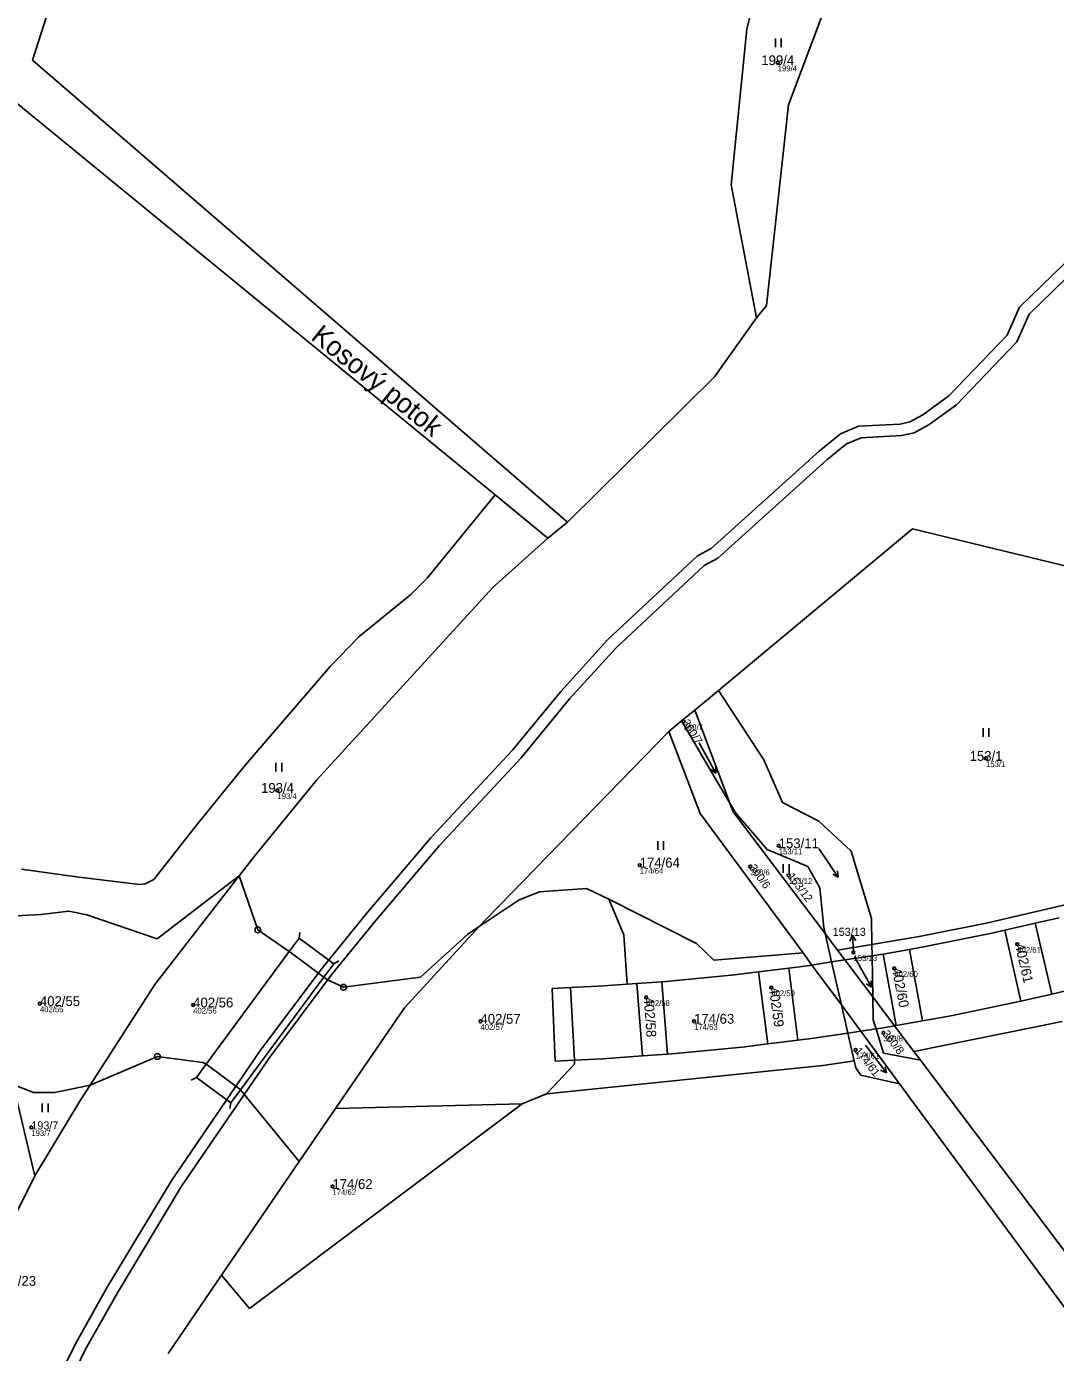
# Model space of a CAD drawing. Extents: x -868010 to -864567, y -1041968 to -1040406.
# Drawn here: x -867083.8 to -866905.6, y -1041242.1 to -1041012.6 of the extents above; entities that cross this region are included whole.
import ezdxf

# ---------------------------------------------------------------- set-up
doc = ezdxf.new("R2010")
doc.units = 0
for name, color, linetype in [('Definiční body', 7, 'Continuous'), ('Hranice parcel', 7, 'Continuous'), ('Parcelní čísla', 7, 'Continuous'), ('Pop  PČ popisy', 7, 'Continuous'), ('Vnitřní kresba', 7, 'Continuous'), ('Věcná břemena k části', 7, 'Continuous'), ('Značky bodu BP', 7, 'Continuous'), ('Značky kultur', 7, 'Continuous')]:
    doc.layers.add(name, color=color, linetype=linetype)

msp = doc.modelspace()

# ---------------------------------------------------------------- linework, layer by layer
at = {"layer": 'Definiční body'}
for centre in [(-866953.73, -1041018.85994), (-866970.03, -1041132.88994), (-866917.66, -1041139.30994), (-867040.36, -1041144.83994), (-866953.56, -1041154.41994), (-866977.63, -1041157.77994), (-866958.47, -1041158.02994), (-866951.83, -1041159.53994), (-866912.25, -1041171.46994), (-866940.61, -1041172.88994), (-866933.55, -1041175.64994), (-866954.84, -1041178.96994), (-867081.49, -1041181.74994), (-866976.5, -1041180.66994), (-867054.95, -1041181.98994), (-867005.2, -1041184.81994), (-866968.21, -1041184.80994), (-866935.42, -1041186.79994), (-866940.24, -1041189.77994), (-867082.98, -1041203.18994), (-867030.83, -1041213.41994)]:
    msp.add_circle(centre, 0.25, dxfattribs=at)
at = {"layer": 'Hranice parcel'}
for p, q in [((-867082.76, -1041018.41), (-867069.5, -1040976.72)), ((-866956.53, -1041002.58), (-866959.05, -1041013.05)), ((-866951.89, -1041026.16), (-866945.61, -1041009.62)), ((-866959.05, -1041013.05), (-866961.8, -1041040.03)), ((-866990.14, -1041098.41), (-867082.76, -1041018.41)), ((-867002.66, -1041093.69), (-867091.88, -1041020.67)), ((-866955.7, -1041060.91), (-866951.89, -1041026.16)), ((-866961.8, -1041040.03), (-866957.38, -1041063.05)), ((-866957.38, -1041063.05), (-866955.7, -1041060.91)), ((-866957.38, -1041063.05), (-866964.69, -1041073.26)), ((-866964.69, -1041073.26), (-866990.14, -1041098.41)), ((-867014.44, -1041108.08), (-867002.66, -1041093.69)), ((-867002.66, -1041093.69), (-866993.56, -1041101.15)), ((-866990.14, -1041098.41), (-866993.56, -1041101.15)), ((-866993.56, -1041101.15), (-867003.04, -1041109.72)), ((-866930.4, -1041099.56), (-866964, -1041127.54)), ((-866899.09, -1041107.19), (-866930.4, -1041099.56)), ((-867017.25, -1041110.9), (-867014.44, -1041108.08)), ((-867003.04, -1041109.72), (-867033.51, -1041142.99)), ((-867026.18, -1041118.21), (-867017.25, -1041110.9)), ((-867031.22, -1041123.37), (-867026.18, -1041118.21)), ((-867045.88, -1041140.4), (-867031.22, -1041123.37)), ((-866964, -1041127.54), (-866968.08, -1041130.93)), ((-866956.12, -1041139.57), (-866964, -1041127.54)), ((-866970.39, -1041132.82), (-866968.08, -1041130.93)), ((-866968.08, -1041130.93), (-866962, -1041147.03)), ((-866970.39, -1041132.82), (-866972.58, -1041134.62)), ((-866962, -1041147.03), (-866970.39, -1041132.82)), ((-866972.58, -1041134.62), (-867004.12, -1041167.01)), ((-866967.16, -1041148.83), (-866972.58, -1041134.62)), ((-867054.17, -1041150.56), (-867045.88, -1041140.4)), ((-866952.89, -1041146.93), (-866956.12, -1041139.57)), ((-867033.51, -1041142.99), (-867044.34, -1041156.21)), ((-866962, -1041147.03), (-866961.42, -1041148.56)), ((-866960.94, -1041148.82), (-866962, -1041147.03)), ((-866946.63, -1041150.18), (-866952.89, -1041146.93)), ((-866949.34, -1041172.98), (-866967.16, -1041148.83)), ((-866961.42, -1041148.56), (-866945.53, -1041169.61)), ((-866955.53, -1041155.07), (-866960.94, -1041148.82)), ((-867061.75, -1041160.24), (-867054.17, -1041150.56)), ((-866941.03, -1041155.38), (-866946.63, -1041150.18)), ((-867047.01, -1041159.66), (-867044.34, -1041156.21)), ((-866948.49, -1041158), (-866955.53, -1041155.07)), ((-866937.5, -1041167), (-866941.03, -1041155.38)), ((-867084.68, -1041158.49), (-867075.15, -1041159.79)), ((-866946.42, -1041161.69), (-866948.49, -1041158)), ((-867075.15, -1041159.79), (-867064.26, -1041161.14)), ((-867064.26, -1041161.14), (-867063.25, -1041161)), ((-867063.25, -1041161), (-867061.75, -1041160.24)), ((-867047.01, -1041159.66), (-867061.59, -1041178.47)), ((-867061.16, -1041170.53), (-867047.01, -1041159.66)), ((-867047.01, -1041159.66), (-867043.78, -1041168.98)), ((-866998.49, -1041163.81), (-866994.96, -1041162.41)), ((-866994.96, -1041162.41), (-866986.85, -1041161.84)), ((-866986.85, -1041161.84), (-866982.98, -1041163.69)), ((-866945.77, -1041168.59), (-866946.42, -1041161.69)), ((-867005.41, -1041168.41), (-866998.49, -1041163.81)), ((-866982.98, -1041163.69), (-866967.78, -1041171.35)), ((-866982.98, -1041163.69), (-866980.36, -1041169.82)), ((-866917.35, -1041167.76), (-866902.75, -1041164.39)), ((-867092.92, -1041166.93), (-867081.27, -1041166.31)), ((-867081.27, -1041166.31), (-867076.5, -1041165.75)), ((-867076.5, -1041165.75), (-867073.35, -1041166.37)), ((-867073.35, -1041166.37), (-867061.16, -1041170.53)), ((-867005.41, -1041168.41), (-867004.12, -1041167.01)), ((-866937.42, -1041171.51), (-866937.5, -1041167)), ((-866929.26, -1041170.14), (-866917.35, -1041167.76)), ((-866914.4, -1041169.04), (-866909.15, -1041167.84)), ((-866909.15, -1041167.84), (-866906.26, -1041180.09)), ((-867043.78, -1041168.98), (-867038.31, -1041172.75)), ((-867018.38, -1041182.48), (-867005.41, -1041168.41)), ((-867015.56, -1041177.2), (-867007.47, -1041169.78)), ((-867007.47, -1041169.78), (-867005.41, -1041168.41)), ((-866980.36, -1041169.82), (-866979.81, -1041178.4)), ((-866945.53, -1041169.61), (-866945.77, -1041168.59)), ((-866944.4, -1041174.54), (-866945.53, -1041169.61)), ((-866945.53, -1041169.61), (-866943.35, -1041172.51)), ((-866937.42, -1041171.51), (-866929.26, -1041170.14)), ((-866914.4, -1041169.04), (-866911.65, -1041181.34)), ((-866967.78, -1041171.35), (-866964.81, -1041174.22)), ((-866937.42, -1041171.51), (-866943.35, -1041172.51)), ((-866943.35, -1041172.51), (-866942.09, -1041174.19)), ((-866937.38, -1041173.46), (-866937.42, -1041171.51)), ((-866935.47, -1041173.17), (-866930.93, -1041172.36)), ((-866928.65, -1041184.72), (-866930.93, -1041172.36)), ((-867038.31, -1041172.75), (-867038.15, -1041172.86)), ((-867038.15, -1041172.86), (-867032.49, -1041177.07)), ((-866964.81, -1041174.22), (-866949.34, -1041172.98)), ((-866947.8, -1041175.07), (-866949.34, -1041172.98)), ((-866944.4, -1041174.54), (-866942.7, -1041181.98)), ((-866937.25, -1041180.6), (-866942.09, -1041174.19)), ((-866937.25, -1041180.6), (-866937.38, -1041173.46)), ((-866935.47, -1041173.17), (-866933.23, -1041185.53)), ((-867032.49, -1041177.07), (-867032.33, -1041177.18)), ((-866957.06, -1041176.27), (-866951.81, -1041175.62)), ((-866955.45, -1041188.74), (-866957.06, -1041176.27)), ((-866951.81, -1041175.62), (-866950.24, -1041188.09)), ((-866942.7, -1041181.98), (-866947.8, -1041175.07)), ((-867061.59, -1041178.47), (-867072.8, -1041195.85)), ((-867032.33, -1041177.18), (-867031.71, -1041177.62)), ((-867031.71, -1041177.62), (-867028.91, -1041178.93)), ((-867028.91, -1041178.93), (-867015.56, -1041177.2)), ((-866984.83, -1041178.76), (-866989.6, -1041178.99)), ((-866988.94, -1041191.53), (-866989.6, -1041178.99)), ((-866979.81, -1041178.4), (-866984.83, -1041178.76)), ((-866978.14, -1041178.28), (-866973.8, -1041177.97)), ((-866977.14, -1041190.81), (-866978.14, -1041178.28)), ((-866973.8, -1041177.97), (-866972.83, -1041190.51)), ((-866937.18, -1041184.59), (-866937.25, -1041180.6)), ((-866933.49, -1041185.58), (-866937.25, -1041180.6)), ((-866911.65, -1041181.34), (-866906.26, -1041180.09)), ((-867030.33, -1041199.93), (-867018.38, -1041182.48)), ((-866942.7, -1041181.98), (-866941.58, -1041186.86)), ((-866939.35, -1041186.52), (-866942.7, -1041181.98)), ((-866936.71, -1041186.12), (-866937.18, -1041184.59)), ((-866935.42, -1041190.31), (-866936.71, -1041186.12)), ((-866933.49, -1041185.58), (-866930.14, -1041190.03)), ((-866933.23, -1041185.53), (-866928.65, -1041184.72)), ((-866930.14, -1041190.03), (-866904.46, -1041184.83)), ((-866955.45, -1041188.74), (-866950.24, -1041188.09)), ((-866941.58, -1041186.86), (-866940.48, -1041191.65)), ((-866939.35, -1041186.52), (-866932.62, -1041195.63)), ((-867061.15, -1041190.9), (-867072.8, -1041195.85)), ((-867053.3, -1041191.94), (-867061.15, -1041190.9)), ((-866977.14, -1041190.81), (-866972.83, -1041190.51)), ((-866928.98, -1041191.57), (-866935.42, -1041190.31)), ((-866930.14, -1041190.03), (-866928.98, -1041191.57)), ((-867052.7, -1041192.25), (-867053.3, -1041191.94)), ((-867052.7, -1041192.25), (-867052.53, -1041192.34)), ((-867052.53, -1041192.34), (-867046.86, -1041196.54)), ((-866988.9, -1041192.26), (-866993.76, -1041197.38)), ((-866945.91, -1041192.49), (-866993.76, -1041197.38)), ((-866988.94, -1041191.53), (-866988.9, -1041192.26)), ((-866940.48, -1041191.65), (-866945.91, -1041192.49)), ((-866940.48, -1041191.65), (-866940.2, -1041192.86)), ((-866940.2, -1041192.86), (-866939.33, -1041194.15)), ((-866928.98, -1041191.57), (-866897.74, -1041232.98)), ((-866939.33, -1041194.15), (-866932.62, -1041195.63)), ((-867082.62, -1041197.14), (-867086.1, -1041195.74)), ((-867086.1, -1041195.74), (-867082.35, -1041211.58)), ((-867078.93, -1041197.14), (-867082.62, -1041197.14)), ((-867072.8, -1041195.85), (-867078.93, -1041197.14)), ((-867072.8, -1041195.85), (-867074.43, -1041198.36)), ((-867046.86, -1041196.54), (-867046.75, -1041196.68)), ((-867036.6, -1041209.1), (-867046.75, -1041196.68)), ((-866993.76, -1041197.38), (-866997.96, -1041199.08)), ((-866900.58, -1041239.05), (-866932.62, -1041195.63)), ((-867074.43, -1041198.36), (-867082.35, -1041211.58)), ((-866997.96, -1041199.08), (-867045.2, -1041234.53)), ((-867030.33, -1041199.93), (-867036.6, -1041209.1)), ((-866997.96, -1041199.08), (-867030.33, -1041199.93)), ((-867036.6, -1041209.1), (-867050.04, -1041228.77)), ((-867082.35, -1041211.58), (-867088.51, -1041223.8)), ((-867050.04, -1041228.77), (-867059.3, -1041242.32)), ((-867045.2, -1041234.53), (-867050.04, -1041228.77))]:
    msp.add_line(p, q, dxfattribs=at)
at = {"layer": 'Pop  PČ popisy'}
for p, q in [((-866940.767, -1041169.893), (-866941.215, -1041170.919)), ((-866940.61, -1041172.89), (-866940.767, -1041169.893)), ((-866940.767, -1041169.893), (-866940.215, -1041170.867))]:
    msp.add_line(p, q, dxfattribs=at)
at = {"layer": 'Vnitřní kresba'}
for p, q in [((-866905, -1041166.89), (-866909.15, -1041167.84)), ((-867036.47, -1041169.459), (-867036.609, -1041170.45)), ((-866916.66, -1041169.56), (-866928.21, -1041171.88)), ((-866914.4, -1041169.04), (-866916.66, -1041169.56)), ((-867038.31, -1041172.75), (-867036.61, -1041170.45)), ((-867036.61, -1041170.45), (-867030.61, -1041174.86)), ((-866928.21, -1041171.88), (-866930.93, -1041172.36)), ((-867052.7, -1041192.25), (-867038.31, -1041172.75)), ((-867029.752, -1041174.345), (-867030.609, -1041174.86)), ((-866944.4, -1041174.54), (-866947.8, -1041175.07)), ((-866942.09, -1041174.19), (-866944.4, -1041174.54)), ((-866937.38, -1041173.46), (-866942.09, -1041174.19)), ((-866935.47, -1041173.17), (-866937.38, -1041173.46)), ((-867030.61, -1041174.86), (-867032.33, -1041177.18)), ((-866961.21, -1041176.79), (-866973.07, -1041177.92)), ((-866957.06, -1041176.27), (-866961.21, -1041176.79)), ((-866949.52, -1041175.33), (-866951.81, -1041175.62)), ((-866947.8, -1041175.07), (-866949.52, -1041175.33)), ((-867032.33, -1041177.18), (-867046.75, -1041196.68)), ((-866989.6, -1041178.99), (-866992.76, -1041179.14)), ((-866992.76, -1041179.14), (-866992.27, -1041191.69)), ((-866978.14, -1041178.28), (-866979.81, -1041178.4)), ((-866973.07, -1041177.92), (-866973.8, -1041177.97)), ((-866906.26, -1041180.09), (-866899.93, -1041178.61)), ((-866923.77, -1041183.86), (-866911.65, -1041181.34)), ((-866928.65, -1041184.72), (-866923.77, -1041183.86)), ((-866939.35, -1041186.52), (-866936.71, -1041186.12)), ((-866936.71, -1041186.12), (-866935.75, -1041185.98)), ((-866935.75, -1041185.98), (-866933.49, -1041185.58)), ((-866933.49, -1041185.58), (-866933.23, -1041185.53)), ((-866950.24, -1041188.09), (-866947.87, -1041187.8)), ((-866947.87, -1041187.8), (-866941.58, -1041186.86)), ((-866941.58, -1041186.86), (-866939.35, -1041186.52)), ((-866984.07, -1041191.3), (-866977.14, -1041190.81)), ((-866972.83, -1041190.51), (-866972.04, -1041190.45)), ((-866972.04, -1041190.45), (-866959.87, -1041189.29)), ((-866959.87, -1041189.29), (-866955.45, -1041188.74)), ((-867054.39, -1041194.54), (-867052.7, -1041192.25)), ((-866992.27, -1041191.69), (-866988.94, -1041191.53)), ((-866988.94, -1041191.53), (-866984.07, -1041191.3)), ((-867055.289, -1041194.978), (-867054.391, -1041194.54)), ((-867048.43, -1041198.95), (-867054.39, -1041194.54)), ((-867046.75, -1041196.68), (-867048.43, -1041198.95)), ((-867048.604, -1041199.935), (-867048.431, -1041198.95))]:
    msp.add_line(p, q, dxfattribs=at)
at = {"layer": 'Věcná břemena k části'}
for points in [[(-866854.38, -1041006.6), (-866868.68, -1041019.76), (-866882.22, -1041033.36), (-866890.82, -1041040.78), (-866911.84, -1041061.21), (-866913.99, -1041066.06), (-866924.08, -1041076.56), (-866928.61, -1041079.8), (-866930.84, -1041081.06), (-866932.53, -1041081.42), (-866939.75, -1041081.81), (-866942.88, -1041083.13), (-866946.55, -1041086.11), (-866965.25, -1041102.99), (-866967.63, -1041104.22), (-866983.14, -1041118.72), (-866991.28, -1041127.71), (-866999.65, -1041137.89), (-867013.79, -1041153.08), (-867024.92, -1041166.14)], [(-867077.92, -1041250.54), (-867073.57, -1041241.57), (-867068.08, -1041231.83), (-867056.96, -1041213.35), (-867041.67, -1041191.01), (-867031.03, -1041176.85), (-867023.38, -1041167.42), (-867012.29, -1041154.4), (-866998.15, -1041139.21), (-866989.76, -1041129.01), (-866981.72, -1041120.14), (-866966.49, -1041105.88), (-866964.11, -1041104.65), (-866945.25, -1041087.63), (-866941.84, -1041084.87), (-866939.29, -1041083.79), (-866932.27, -1041083.4), (-866930.12, -1041082.96), (-866927.53, -1041081.48), (-866922.76, -1041078.08), (-866912.31, -1041067.2), (-866910.16, -1041062.37), (-866889.48, -1041042.26)], [(-867024.92, -1041166.14), (-867032.61, -1041175.61), (-867043.29, -1041189.83), (-867058.66, -1041212.29), (-867069.82, -1041230.83), (-867075.35, -1041240.65), (-867079.76, -1041249.74)]]:
    msp.add_lwpolyline(points, dxfattribs=at)
at = {"layer": 'Značky bodu BP'}
for centre, radius in [((-867043.78, -1041168.97988), 0.5), ((-867043.78, -1041168.97988), 0.0303), ((-867028.91, -1041178.92988), 0.5), ((-867028.91, -1041178.92988), 0.0303), ((-867061.15, -1041190.89988), 0.5), ((-867061.15, -1041190.89988), 0.0303)]:
    msp.add_circle(centre, radius, dxfattribs=at)
at = {"layer": 'Značky kultur'}
for p, q in [((-866954.141, -1041016.16), (-866954.141, -1041014.66)), ((-866953.14, -1041016.16), (-866953.14, -1041014.66)), ((-866918.171, -1041135.59), (-866918.171, -1041134.09)), ((-866917.17, -1041135.59), (-866917.17, -1041134.09)), ((-866967.334, -1041136.615), (-866964.425, -1041141.863)), ((-867040.611, -1041141.59), (-867040.611, -1041140.09)), ((-867039.61, -1041141.59), (-867039.61, -1041140.09)), ((-866964.425, -1041141.863), (-866965.337, -1041141.251)), ((-866964.425, -1041141.863), (-866964.46, -1041140.765)), ((-866974.481, -1041155.16), (-866974.481, -1041153.66)), ((-866973.48, -1041155.16), (-866973.48, -1041153.66)), ((-866946.595, -1041154.892), (-866943.24, -1041159.866)), ((-866952.771, -1041159.1), (-866952.771, -1041157.6)), ((-866951.77, -1041159.1), (-866951.77, -1041157.6)), ((-866943.24, -1041159.866), (-866943.371, -1041158.776)), ((-866943.24, -1041159.866), (-866944.202, -1041159.336)), ((-866940.424, -1041173.665), (-866937.515, -1041178.913)), ((-866937.515, -1041178.913), (-866938.427, -1041178.301)), ((-866937.515, -1041178.913), (-866937.55, -1041177.815)), ((-866938.532, -1041188.963), (-866934.921, -1041193.755)), ((-866934.921, -1041193.755), (-866935.109, -1041192.673)), ((-866934.921, -1041193.755), (-866935.91, -1041193.276)), ((-867081.081, -1041200.53), (-867081.081, -1041199.03)), ((-867080.08, -1041200.53), (-867080.08, -1041199.03))]:
    msp.add_line(p, q, dxfattribs=at)

# ---------------------------------------------------------------- texts
at = {"layer": 'Definiční body'}
for s, p in [('199/4', (-866953.73, -1041020.349)), ('360/7', (-866970.03, -1041134.379)), ('153/1', (-866917.66, -1041140.799)), ('193/4', (-867040.36, -1041146.329)), ('153/11', (-866953.56, -1041155.909)), ('174/64', (-866977.63, -1041159.269)), ('360/6', (-866958.47, -1041159.519)), ('153/12', (-866951.83, -1041161.029)), ('402/61', (-866912.25, -1041172.959)), ('153/13', (-866940.61, -1041174.379)), ('402/60', (-866933.55, -1041177.139)), ('402/59', (-866954.84, -1041180.459)), ('402/58', (-866976.5, -1041182.159)), ('402/55', (-867081.49, -1041183.239)), ('402/56', (-867054.95, -1041183.479)), ('402/57', (-867005.2, -1041186.309)), ('174/63', (-866968.21, -1041186.299)), ('360/8', (-866935.42, -1041188.289)), ('174/61', (-866940.24, -1041191.269)), ('193/7', (-867082.98, -1041204.679)), ('174/62', (-867030.83, -1041214.909))]:
    msp.add_text(s, height=0.999996, dxfattribs=at).set_placement(p)
at = {"layer": 'Parcelní čísla'}
for s, height, p in [('199/4', 1.699998, (-866956.566, -1041019.285)), ('153/1', 1.699998, (-866920.496, -1041139.735)), ('193/4', 1.699998, (-867043.196, -1041145.265)), ('153/11', 1.699998, (-866953.56, -1041154.845)), ('174/64', 1.699998, (-866977.63, -1041158.205)), ('153/13', 1.399998, (-866944.209, -1041170.03)), ('402/55', 1.699998, (-867081.49, -1041182.175)), ('402/56', 1.699998, (-867054.95, -1041182.415)), ('402/57', 1.699998, (-867005.2, -1041185.245)), ('174/63', 1.699998, (-866968.21, -1041185.235)), ('193/7', 1.399998, (-867082.98, -1041203.54)), ('174/62', 1.699998, (-867030.83, -1041213.845)), ('402/23', 1.699998, (-867089.116, -1041230.605))]:
    msp.add_text(s, height=height, dxfattribs=at).set_placement(p)
for s, height, rotation, p in [('360/7', 1.399998, 302, (-866970.326, -1041133.075)), ('360/6', 1.399998, 306, (-866958.753, -1041158.235)), ('153/12', 1.399998, 307, (-866952.109, -1041159.75)), ('402/61', 1.699998, 283, (-866912.664, -1041171.565)), ('402/60', 1.699998, 281, (-866933.967, -1041175.731)), ('402/59', 1.699998, 278, (-866955.26, -1041179.029)), ('402/58', 1.699998, 274, (-866976.923, -1041180.699)), ('360/8', 1.399998, 308, (-866935.695, -1041187.015)), ('174/61', 1.399998, 308, (-866940.515, -1041189.995))]:
    msp.add_text(s, height=height, rotation=rotation, dxfattribs=at).set_placement(p)
at = {"layer": 'Pop  PČ popisy'}
msp.add_text('Kosový potok', height=3.399996, rotation=321, dxfattribs=at).set_placement((-867034.748, -1041066.624))

doc.saveas('drawing.dxf')
